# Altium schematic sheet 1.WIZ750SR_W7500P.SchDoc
size A4; DrawnBy: Edward; Organization: WIZnet Co., Ltd.; Address1: 5F, Humax Village; Address2: Hwangseaul-ro, Bundang-Gu; Address3: Seongnam-Si, Gyeonggi-Do; Address4: South Korea; Team: CS
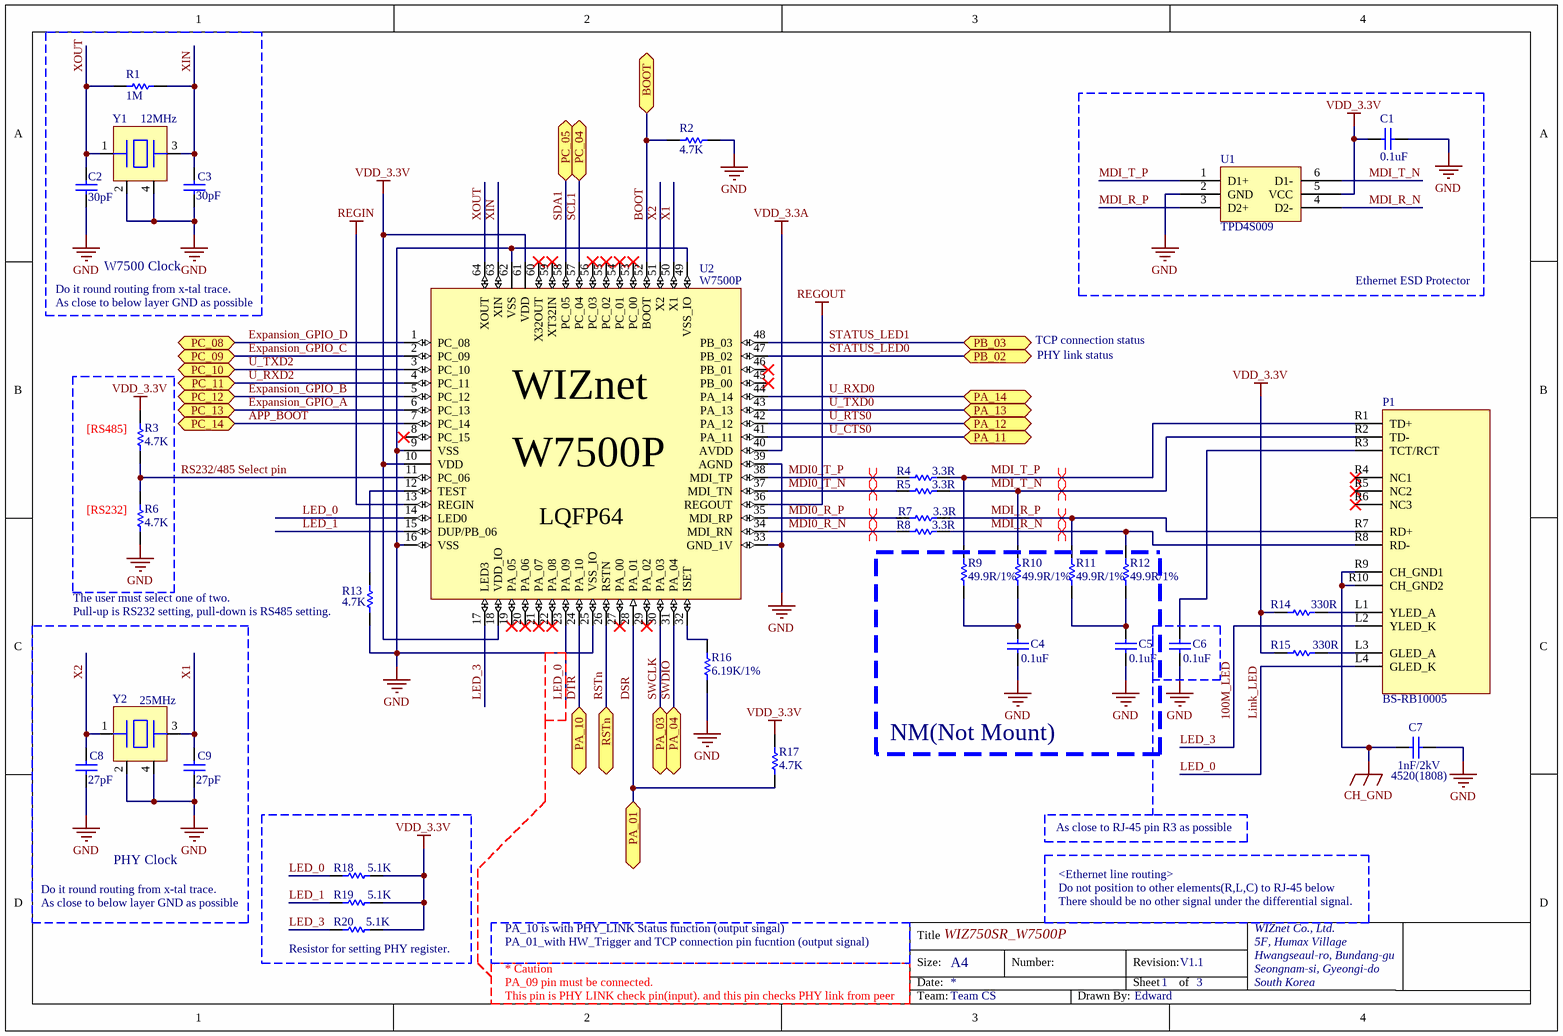
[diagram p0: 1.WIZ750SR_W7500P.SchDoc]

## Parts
C1  0.1uF  [CAP-0402]
C2  30pF  [CAP-0402]
C3  30pF  [CAP-0402]
C4  0.1uF  [CAP-0402]
C5  0.1uF  [CAP-0402]
C6  0.1uF  [CAP-0402]
C7  1nF/2kV  [CAP-1808]
C8  27pF  [CAP-0402]
C9  27pF  [CAP-0402]
P1  BS-RB10005  [RJ45-125BAG1A]
R1  1M  [RES-0402]
R2  4.7K  [RES-0402]
R3  4.7K  [RES-0402]
R4  3.3R  [RES-0402]
R5  3.3R  [RES-0402]
R6  4.7K  [RES-0402]
R7  3.3R  [RES-0402]
R8  3.3R  [RES-0402]
R9  49.9R/1%  [RES-0402]
R10  49.9R/1%  [RES-0402]
R11  49.9R/1%  [RES-0402]
R12  49.9R/1%  [RES-0402]
R13  4.7K  [RES-0402]
R14  330R  [RES-0402]
R15  330R  [RES-0402]
R16  6.19K/1%  [RES-0402]
R17  4.7K  [RES-0402]
R18  5.1K  [RES-0402]
R19  5.1K  [RES-0402]
R20  5.1K  [RES-0402]
U1  TPD4S009  [SOT-23-6L]
U2  W7500P  [W7500-LQFP64]
Y1  12MHz  [OSC-TZ1067B]
Y2  25MHz  [OSC-82J0626]

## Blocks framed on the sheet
W7500 Clock: C2 C3 R1 Y1
Ethernet ESD Protector: C1 U1
PHY Clock: C8 C9 Y2

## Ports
BOOT, PA_01, PA_03, PA_04, PA_10, PA_11, PA_12, PA_13, PA_14, PB_02, PB_03, PC_04, PC_05, PC_08, PC_09, PC_10, PC_11, PC_12, PC_13, PC_14, RSTn

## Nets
CH_GND: C7.2 P1.R9(CH_GND1) P1.R10(CH_GND2)
GND: C1.1 C2.1 C3.1 C4.1 C5.1 C6.1 C7.1 C8.1 C9.1 R2.1 R6.1 R13.1 R16.1 U1.2(GND) U2.9(VSS) U2.16(VSS) U2.25(VSS_IO) U2.33(GND_1V) U2.39(AGND) U2.49(VSS_IO) U2.62(VSS) Y1.2 Y1.4 Y2.2 Y2.4
REGIN: U2.13(REGIN)
REGOUT: U2.36(REGOUT)
VDD_3.3A: U2.40(AVDD)
VDD_3.3V: C1.2 R3.2 R14.1 R15.1 R17.1 R18.2 R19.2 R20.2 U1.5(VCC) U2.10(VDD) U2.18(VDD_IO) U2.61(VDD)
100M_LED: P1.L2(YLED_K) R20.1 U2.17(LED3)  [also labelled LED_3]
APP_BOOT: U2.7(PC_14) ; port PC_14
BOOT: R2.2 U2.52(BOOT) ; port BOOT
DSR: R17.2 U2.28(PA_01) ; port PA_01
DTR: U2.24(PA_10) ; port PA_10
Expansion_GPIO_A: U2.6(PC_13) ; port PC_13
Expansion_GPIO_B: U2.5(PC_12) ; port PC_12
Expansion_GPIO_C: U2.2(PC_09) ; port PC_09
Expansion_GPIO_D: U2.1(PC_08) ; port PC_08
LED_0: P1.L4(GLED_K) R18.1 U2.14(LED0) U2.23(PA_09)  [also labelled Link_LED]
LED_1: R19.1 U2.15(DUP/PB_06)
MDI0_R_N: R8.1 U2.34(MDI_RN)
MDI0_R_P: R7.1 U2.35(MDI_RP)
MDI0_T_N: R5.1 U2.37(MDI_TN)
MDI0_T_P: R4.1 U2.38(MDI_TP)
MDI_R_N: P1.R8(RD-) R8.2 R12.2 U1.4(D2-)
MDI_R_P: P1.R7(RD+) R7.2 R11.2 U1.3(D2+)
MDI_T_N: P1.R2(TD-) R5.2 R10.2 U1.6(D1-)
MDI_T_P: P1.R1(TD+) R4.2 R9.2 U1.1(D1+)
RS232/485 Select pin: R3.1 R6.2 U2.11(PC_06)
RSTn: U2.26(RSTN) ; port RSTn
SCL1: U2.57(PC_04) ; port PC_04
SDA1: U2.58(PC_05) ; port PC_05
STATUS_LED0: U2.47(PB_02) ; port PB_02
STATUS_LED1: U2.48(PB_03) ; port PB_03
SWCLK: U2.30(PA_03) ; port PA_03
SWDIO: U2.31(PA_04) ; port PA_04
U_CTS0: U2.41(PA_11) ; port PA_11
U_RTS0: U2.42(PA_12) ; port PA_12
U_RXD0: U2.44(PA_14) ; port PA_14
U_RXD2: U2.4(PC_11) ; port PC_11
U_TXD0: U2.43(PA_13) ; port PA_13
U_TXD2: U2.3(PC_10) ; port PC_10
X1: C9.2 U2.50(X1) Y2.3
X2: C8.2 U2.51(X2) Y2.1
XIN: C3.2 R1.2 U2.63(XIN) Y1.3
XOUT: C2.2 R1.1 U2.64(XOUT) Y1.1
NetC4_2: C4.2 R9.1 R10.1
NetC5_2: C5.2 R11.1 R12.1
NetC6_2: C6.2 P1.R3(TCT/RCT)
NetP1_L1: P1.L1(YLED_A) R14.2
NetP1_L3: P1.L3(GLED_A) R15.2
NetR13_2: R13.2 U2.12(TEST)
NetR16_2: R16.2 U2.32(ISET)

Not connected (* = marked no-connect by the designer): P1 R4(NC1)* R5(NC2)* R6(NC3)*; U2 8(PC_15)* 19(PA_05)* 20(PA_06)* 21(PA_07)* 22(PA_08)* 27(PA_00)* 29(PA_02)* 45(PB_00)* 46(PB_01)* 53(PC_00)* 54(PC_01)* 55(PC_02)* 56(PC_03)* 59(XT32IN)* 60(X32OUT)*

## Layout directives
differential pair: MDI0_R_N, MDI0_R_P, MDI0_T_N, MDI0_T_P, MDI_R_N, MDI_R_P, MDI_T_N, MDI_T_P

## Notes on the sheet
- Do it round routing from x-tal trace.
- As close to below layer GND as possible
- TCP connection status
- PHY link status
- (near R3) [RS485]
- (near R6) [RS232]
- The user must select one of two.
- (near R13) Pull-up is RS232 setting, pull-down is RS485 setting.
- NM(Not Mount)
- (near C7) 4520(1808)
- As close to RJ-45 pin R3 as possible
- <Ethernet line routing>
- Do not position to other elements(R,L,C) to RJ-45 below
- There should be no other signal under the differential signal.
- (near R20) Resistor for setting PHY register.
- * Caution
- PA_09 pin must be connected.
- PA_01_with HW_Trigger and TCP connection pin fucntion (output signal)
- PA_10 is with PHY_LINK Status function (output singal)
- Title
- Size:
- Date:
- WIZ750SR_W7500P
- A4
- Number:
- Revision:
- Sheet
- 1
- of
- V1.1
- 3
- WIZnet Co., Ltd.
- 5F, Humax Village
- Hwangseaul-ro, Bundang-gu
- Seongnam-si, Gyeongi-do
- South Korea
- This pin is PHY LINK check pin(input). and this pin checks PHY link from peer
- Team:
- Team CS
- Drawn By:
- Edward

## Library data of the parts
C1-C6 C8 C9 = CAP-0402: Ceramic CAP 0402(1005)
C7 = CAP-1808: Ceramic CAP 1808(4520)
P1 = RB1-125BAG1A: 10/100 BASE-TX MAGJACK
R1-R20 = RES-0402
U1 = tpd4s009: 6-PIN SOT DBVor DCK Package
U2 = W7500P: WIZnet ARM Cortex-M0, Add PHY
Y1 = OSC-TZ1067B-12MHz: X-tal 12MHz,3.2x2.5 SMD, CL=20pF
Y2 = OSC-82J0626-25MHz: X-tal 25MHz,3.2x2.5 SMD, CL=18pF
